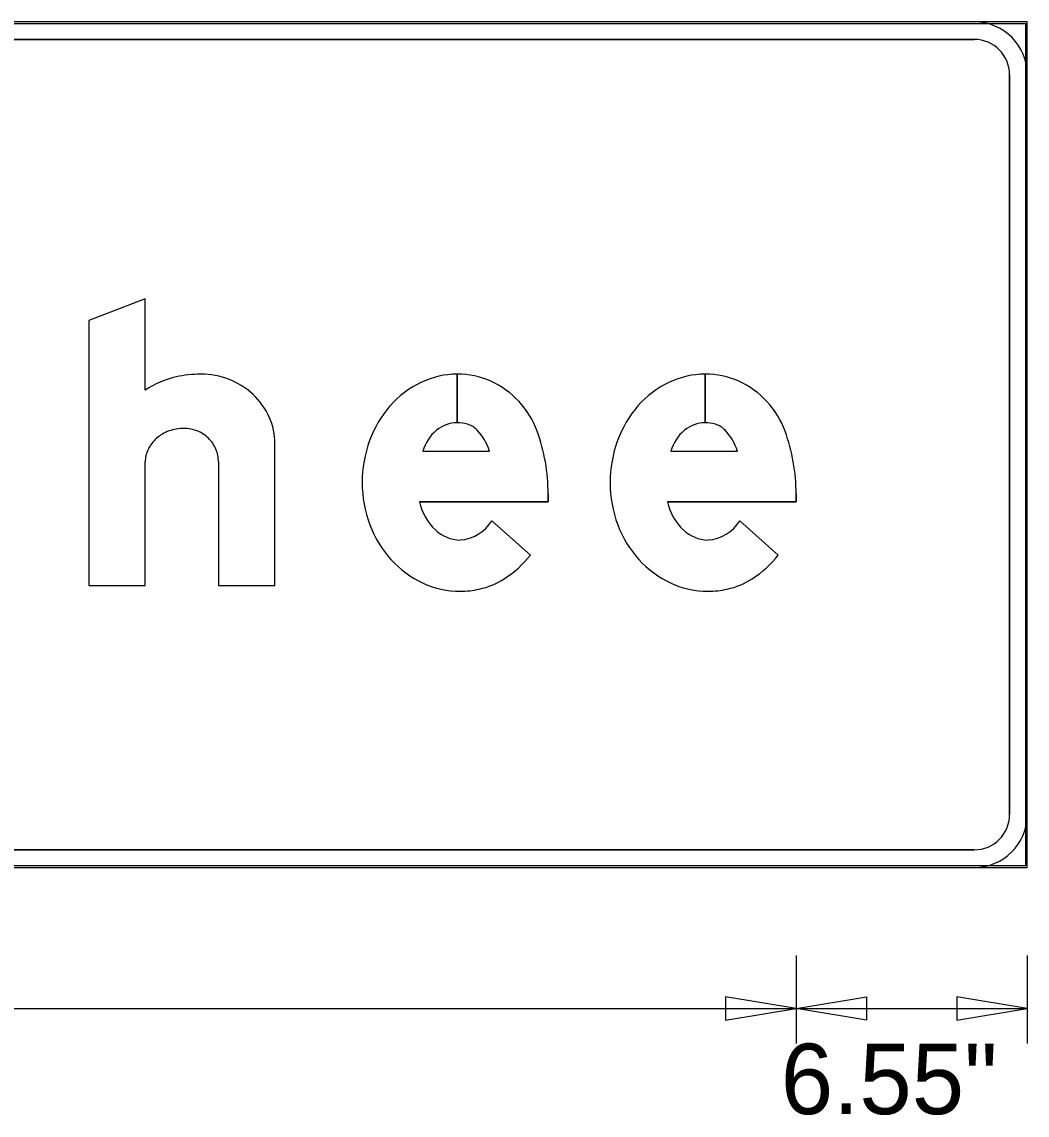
# Model space of a CAD drawing. Extents: x 1374 to 1480, y 568 to 638.
# Drawn here: x 1420.479 to 1422.858, y 581.697 to 584.283 of the extents above; entities that cross this region are included whole.
import ezdxf

# ---------------------------------------------------------------- set-up
doc = ezdxf.new("R2010")
doc.units = 0
for name, color, linetype in [('GSBWFill', 7, 'Continuous'), ('GSColorFill', 7, 'Continuous'), ('GSDims', 7, 'Continuous'), ('GSOutline', 7, 'Continuous')]:
    doc.layers.add(name, color=color, linetype=linetype)

msp = doc.modelspace()

# ---------------------------------------------------------------- linework, layer by layer
at = {"layer": 'GSBWFill'}
for p, q in [((1422.8581, 584.2826), (1415.8581, 584.2826)), ((1422.7331, 584.2826), (1415.9831, 584.2826)), ((1422.8581, 582.2826), (1422.8581, 584.2826)), ((1415.9831, 584.2409), (1422.7331, 584.2409)), ((1422.8164, 584.1576), (1422.8164, 582.4076)), ((1422.8581, 582.4076), (1422.8581, 584.1576)), ((1421.5094, 583.4492), (1421.5094, 583.3342)), ((1421.5094, 583.3342), (1421.5094, 583.4492)), ((1422.0961, 583.4492), (1422.0961, 583.3342)), ((1422.0961, 583.3342), (1422.0961, 583.4492)), ((1421.4281, 583.2674), (1421.586, 583.2674)), ((1422.0147, 583.2674), (1422.1727, 583.2674)), ((1421.5913, 583.1023), (1421.6826, 583.0215)), ((1422.178, 583.1023), (1422.2693, 583.0215)), ((1422.7331, 582.3242), (1415.9835, 582.3242)), ((1415.8581, 582.2826), (1422.8581, 582.2826)), ((1415.9835, 582.2826), (1422.7331, 582.2826))]:
    msp.add_line(p, q, dxfattribs=at)
for points in [[(1420.7714, 583.4118), (1420.7714, 583.6276), (1420.6381, 583.5761), (1420.6381, 582.9492), (1420.7714, 582.9492), (1420.7714, 583.2416)], [(1420.9447, 583.2416), (1420.9447, 582.9492), (1421.0781, 582.9492), (1421.0781, 583.2855)], [(1421.7247, 583.1664), (1421.7247, 583.1474), (1421.4205, 583.1474)], [(1422.3114, 583.1664), (1422.3114, 583.1474), (1422.0071, 583.1474)]]:
    msp.add_lwpolyline(points, dxfattribs=at)
for centre, radius, start, end in [((1422.7331, 584.1576), 0.125, 0, 90), ((1422.7331, 584.1576), 0.0833, 0, 90), ((1422.7331, 582.4076), 0.125, 270, 0), ((1422.7331, 582.4076), 0.0833, 270, 0)]:
    msp.add_arc(centre, radius, start, end, dxfattribs=at)
for centre, major_axis, start_param, end_param in [((1420.9004, 583.2093), (0, 0.2401), 0.235088, 0.567132), ((1420.9026, 583.1825), (0, 0.2667), 0, 0.219986), ((1420.9026, 583.2615), (0, 0.1877), 5.914285, 6.283185), ((1421.5094, 583.2518), (0, 0.1975), 0, 0.44196), ((1421.5094, 583.2518), (0, 0.1975), 5.868518, 6.283016), ((1422.0961, 583.2518), (0, 0.1975), 0, 0.44196), ((1422.0961, 583.2518), (0, 0.1975), 5.868518, 6.283016), ((1420.9072, 583.2732), (0, 0.1752), 5.532258, 5.914285), ((1421.523, 583.2231), (0, 0.2292), 0.44196, 0.851746), ((1421.5044, 583.2439), (0, 0.2067), 5.061282, 5.861635), ((1422.1096, 583.2231), (0, 0.2292), 0.44196, 0.851746), ((1422.0911, 583.2439), (0, 0.2067), 5.061282, 5.861635), ((1420.9141, 583.2807), (0, 0.1649), 5.130076, 5.532258), ((1421.5441, 583.2046), (0, 0.2573), 0.851746, 1.222943), ((1422.1308, 583.2046), (0, 0.2573), 0.851746, 1.222943), ((1420.925, 583.2855), (0, 0.1531), 4.712389, 5.130076), ((1420.8584, 583.2286), (0, 0.0917), 0.345704, 0.715718), ((1420.8629, 583.2162), (0, 0.105), 0, 0.345704), ((1420.8629, 583.2369), (0, 0.0842), 5.900624, 6.283185), ((1420.8638, 583.2392), (0, 0.0818), 5.51227, 5.900624), ((1421.5283, 583.2369), (0, 0.1047), 0.703138, 1.275447), ((1421.5094, 583.2569), (0, 0.0773), 0, 0.684319), ((1421.5094, 583.2446), (0, 0.0896), 6.008019, 6.282813), ((1421.5202, 583.2827), (0, 0.05), 5.468651, 6.008019), ((1421.4606, 583.2265), (0, 0.132), 5.027692, 5.468651), ((1421.2914, 583.1664), (0, 0.4333), 4.712389, 5.061282), ((1422.115, 583.2369), (0, 0.1047), 0.703138, 1.275447), ((1422.0961, 583.2569), (0, 0.0773), 0, 0.684319), ((1422.0961, 583.2446), (0, 0.0896), 6.008019, 6.282813), ((1422.1068, 583.2827), (0, 0.05), 5.468651, 6.008019), ((1422.0472, 583.2265), (0, 0.132), 5.027692, 5.468651), ((1421.8781, 583.1664), (0, 0.4333), 4.712389, 5.061282), ((1420.8515, 583.2365), (0, 0.0812), 0.715718, 1.126231), ((1420.8652, 583.2407), (0, 0.0797), 5.115435, 5.51227), ((1421.5773, 583.1926), (0, 0.2926), 1.222943, 1.570796), ((1422.164, 583.1926), (0, 0.2926), 1.222943, 1.570796), ((1420.8408, 583.2416), (0, 0.0694), 1.126231, 1.570796), ((1420.8674, 583.2416), (0, 0.0773), 4.712389, 5.115435), ((1421.5685, 583.1926), (0, 0.2838), 1.570796, 1.928626), ((1422.1552, 583.1926), (0, 0.2838), 1.570796, 1.928626), ((1421.5486, 583.1757), (0, 0.1312), 1.788032, 2.378697), ((1422.1352, 583.1757), (0, 0.1312), 1.788032, 2.378697), ((1421.5099, 583.1526), (0, 0.0957), 3.209537, 4.158837), ((1422.0966, 583.1526), (0, 0.0957), 3.209537, 4.158837), ((1421.5431, 583.1831), (0, 0.2567), 1.928626, 2.305123), ((1421.5176, 583.1439), (0, 0.0868), 2.383204, 3.128268), ((1422.1298, 583.1831), (0, 0.2567), 1.928626, 2.305123), ((1422.1043, 583.1439), (0, 0.0868), 2.383204, 3.128268), ((1421.5269, 583.1684), (0, 0.2348), 2.305123, 2.711411), ((1421.4872, 583.1746), (0, 0.2483), 3.710413, 4.047817), ((1422.1135, 583.1684), (0, 0.2348), 2.305123, 2.711411), ((1422.0738, 583.1746), (0, 0.2483), 3.710413, 4.047817), ((1421.5164, 583.1457), (0, 0.2098), 2.711411, 3.141593), ((1421.5221, 583.1199), (0, 0.1833), 3.35931, 3.710413), ((1422.1031, 583.1457), (0, 0.2098), 2.711411, 3.141593), ((1422.1088, 583.1199), (0, 0.1833), 3.35931, 3.710413), ((1421.5164, 583.1457), (0, 0.2098), 3.141593, 3.35931), ((1422.1031, 583.1457), (0, 0.2098), 3.141593, 3.35931)]:
    msp.add_ellipse(centre, major_axis=major_axis, ratio=0.999996, start_param=start_param, end_param=end_param, dxfattribs=at)
at = {"layer": 'GSColorFill'}
for p, q in [((1422.8581, 584.2826), (1415.8581, 584.2826)), ((1422.8581, 584.2826), (1415.8581, 584.2826)), ((1415.8622, 584.2784), (1422.8539, 584.2784)), ((1422.7331, 584.2826), (1415.9831, 584.2826)), ((1422.8539, 584.2784), (1422.8539, 582.2867)), ((1422.8581, 582.2826), (1422.8581, 584.2826)), ((1422.8581, 582.2826), (1422.8581, 584.2826)), ((1415.9831, 584.2409), (1422.7331, 584.2409)), ((1422.8164, 584.1576), (1422.8164, 582.4076)), ((1422.8581, 582.4076), (1422.8581, 584.1576)), ((1421.5094, 583.4492), (1421.5094, 583.3342)), ((1421.5094, 583.3342), (1421.5094, 583.4492)), ((1422.0961, 583.4492), (1422.0961, 583.3342)), ((1422.0961, 583.3342), (1422.0961, 583.4492)), ((1421.4281, 583.2674), (1421.586, 583.2674)), ((1422.0147, 583.2674), (1422.1727, 583.2674)), ((1421.5913, 583.1023), (1421.6826, 583.0215)), ((1422.178, 583.1023), (1422.2693, 583.0215)), ((1422.7331, 582.3242), (1415.9835, 582.3242)), ((1422.8539, 582.2867), (1415.8581, 582.2867)), ((1415.8581, 582.2826), (1422.8581, 582.2826)), ((1415.8581, 582.2826), (1422.8581, 582.2826)), ((1415.9835, 582.2826), (1422.7331, 582.2826))]:
    msp.add_line(p, q, dxfattribs=at)
for points in [[(1420.7714, 583.4118), (1420.7714, 583.6276), (1420.6381, 583.5761), (1420.6381, 582.9492), (1420.7714, 582.9492), (1420.7714, 583.2416)], [(1420.9447, 583.2416), (1420.9447, 582.9492), (1421.0781, 582.9492), (1421.0781, 583.2855)], [(1421.7247, 583.1664), (1421.7247, 583.1474), (1421.4205, 583.1474)], [(1422.3114, 583.1664), (1422.3114, 583.1474), (1422.0071, 583.1474)]]:
    msp.add_lwpolyline(points, dxfattribs=at)
for centre, radius, start, end in [((1422.7331, 584.1576), 0.125, 0, 90), ((1422.7331, 584.1576), 0.0833, 0, 90), ((1422.7331, 582.4076), 0.125, 270, 0), ((1422.7331, 582.4076), 0.0833, 270, 0)]:
    msp.add_arc(centre, radius, start, end, dxfattribs=at)
for centre, major_axis, start_param, end_param in [((1420.9004, 583.2093), (0, 0.2401), 0.235088, 0.567132), ((1420.9026, 583.1825), (0, 0.2667), 0, 0.219986), ((1420.9026, 583.2615), (0, 0.1877), 5.914285, 6.283185), ((1421.5094, 583.2518), (0, 0.1975), 0, 0.44196), ((1421.5094, 583.2518), (0, 0.1975), 5.868518, 6.283016), ((1422.0961, 583.2518), (0, 0.1975), 0, 0.44196), ((1422.0961, 583.2518), (0, 0.1975), 5.868518, 6.283016), ((1420.9072, 583.2732), (0, 0.1752), 5.532258, 5.914285), ((1421.523, 583.2231), (0, 0.2292), 0.44196, 0.851746), ((1421.5044, 583.2439), (0, 0.2067), 5.061282, 5.861635), ((1422.1096, 583.2231), (0, 0.2292), 0.44196, 0.851746), ((1422.0911, 583.2439), (0, 0.2067), 5.061282, 5.861635), ((1420.9141, 583.2807), (0, 0.1649), 5.130076, 5.532258), ((1421.5441, 583.2046), (0, 0.2573), 0.851746, 1.222943), ((1422.1308, 583.2046), (0, 0.2573), 0.851746, 1.222943), ((1420.925, 583.2855), (0, 0.1531), 4.712389, 5.130076), ((1420.8584, 583.2286), (0, 0.0917), 0.345704, 0.715718), ((1420.8629, 583.2162), (0, 0.105), 0, 0.345704), ((1420.8629, 583.2369), (0, 0.0842), 5.900624, 6.283185), ((1420.8638, 583.2392), (0, 0.0818), 5.51227, 5.900624), ((1421.5283, 583.2369), (0, 0.1047), 0.703138, 1.275447), ((1421.5094, 583.2569), (0, 0.0773), 0, 0.684319), ((1421.5094, 583.2446), (0, 0.0896), 6.008019, 6.282813), ((1421.5202, 583.2827), (0, 0.05), 5.468651, 6.008019), ((1421.4606, 583.2265), (0, 0.132), 5.027692, 5.468651), ((1421.2914, 583.1664), (0, 0.4333), 4.712389, 5.061282), ((1422.115, 583.2369), (0, 0.1047), 0.703138, 1.275447), ((1422.0961, 583.2569), (0, 0.0773), 0, 0.684319), ((1422.0961, 583.2446), (0, 0.0896), 6.008019, 6.282813), ((1422.1068, 583.2827), (0, 0.05), 5.468651, 6.008019), ((1422.0472, 583.2265), (0, 0.132), 5.027692, 5.468651), ((1421.8781, 583.1664), (0, 0.4333), 4.712389, 5.061282), ((1420.8515, 583.2365), (0, 0.0812), 0.715718, 1.126231), ((1420.8652, 583.2407), (0, 0.0797), 5.115435, 5.51227), ((1421.5773, 583.1926), (0, 0.2926), 1.222943, 1.570796), ((1422.164, 583.1926), (0, 0.2926), 1.222943, 1.570796), ((1420.8408, 583.2416), (0, 0.0694), 1.126231, 1.570796), ((1420.8674, 583.2416), (0, 0.0773), 4.712389, 5.115435), ((1421.5685, 583.1926), (0, 0.2838), 1.570796, 1.928626), ((1422.1552, 583.1926), (0, 0.2838), 1.570796, 1.928626), ((1421.5486, 583.1757), (0, 0.1312), 1.788032, 2.378697), ((1422.1352, 583.1757), (0, 0.1312), 1.788032, 2.378697), ((1421.5099, 583.1526), (0, 0.0957), 3.209537, 4.158837), ((1422.0966, 583.1526), (0, 0.0957), 3.209537, 4.158837), ((1421.5431, 583.1831), (0, 0.2567), 1.928626, 2.305123), ((1421.5176, 583.1439), (0, 0.0868), 2.383204, 3.128268), ((1422.1298, 583.1831), (0, 0.2567), 1.928626, 2.305123), ((1422.1043, 583.1439), (0, 0.0868), 2.383204, 3.128268), ((1421.5269, 583.1684), (0, 0.2348), 2.305123, 2.711411), ((1421.4872, 583.1746), (0, 0.2483), 3.710413, 4.047817), ((1422.1135, 583.1684), (0, 0.2348), 2.305123, 2.711411), ((1422.0738, 583.1746), (0, 0.2483), 3.710413, 4.047817), ((1421.5164, 583.1457), (0, 0.2098), 2.711411, 3.141593), ((1421.5221, 583.1199), (0, 0.1833), 3.35931, 3.710413), ((1422.1031, 583.1457), (0, 0.2098), 2.711411, 3.141593), ((1422.1088, 583.1199), (0, 0.1833), 3.35931, 3.710413), ((1421.5164, 583.1457), (0, 0.2098), 3.141593, 3.35931), ((1422.1031, 583.1457), (0, 0.2098), 3.141593, 3.35931)]:
    msp.add_ellipse(centre, major_axis=major_axis, ratio=0.999996, start_param=start_param, end_param=end_param, dxfattribs=at)
at = {"layer": 'GSDims'}
for p, q in [((1422.3114, 582.0742), (1422.3114, 581.8659)), ((1422.3114, 582.0742), (1422.3114, 581.8659)), ((1422.8581, 582.0742), (1422.8581, 581.8659)), ((1422.8581, 582.0742), (1422.8581, 581.8659)), ((1416.4047, 581.9492), (1422.3114, 581.9492)), ((1422.3114, 581.9492), (1422.8581, 581.9492))]:
    msp.add_line(p, q, dxfattribs=at)
for points in [[(1422.3114, 581.9492), (1422.1447, 581.977), (1422.1447, 581.9215)], [(1422.3114, 581.9492), (1422.4781, 581.977), (1422.4781, 581.9215)], [(1422.8581, 581.9492), (1422.6914, 581.977), (1422.6914, 581.9215)]]:
    msp.add_lwpolyline(points, close=True, dxfattribs=at)
at = {"layer": 'GSOutline'}
for p, q in [((1422.8581, 584.2826), (1415.8581, 584.2826)), ((1422.7331, 584.2826), (1415.9831, 584.2826)), ((1422.8581, 582.2826), (1422.8581, 584.2826)), ((1422.7331, 584.2409), (1415.9831, 584.2409)), ((1422.8164, 582.4076), (1422.8164, 584.1576)), ((1422.8581, 582.4076), (1422.8581, 584.1576)), ((1421.4281, 583.2674), (1421.586, 583.2674)), ((1422.0147, 583.2674), (1422.1727, 583.2674)), ((1421.6826, 583.0215), (1421.5913, 583.1023)), ((1422.2693, 583.0215), (1422.178, 583.1023)), ((1415.9831, 582.3242), (1422.7331, 582.3242)), ((1415.8581, 582.2826), (1422.8581, 582.2826)), ((1415.9831, 582.2826), (1422.7331, 582.2826))]:
    msp.add_line(p, q, dxfattribs=at)
for points in [[(1420.7714, 583.4118), (1420.7714, 583.6276), (1420.6381, 583.5761), (1420.6381, 582.9492), (1420.7714, 582.9492), (1420.7714, 583.2416)], [(1420.9447, 583.2416), (1420.9447, 582.9492), (1421.0781, 582.9492), (1421.0781, 583.2855)], [(1421.4205, 583.1474), (1421.7247, 583.1474), (1421.7247, 583.1664)], [(1422.0071, 583.1474), (1422.3114, 583.1474), (1422.3114, 583.1664)]]:
    msp.add_lwpolyline(points, dxfattribs=at)
for centre, radius, start, end in [((1422.7331, 584.1576), 0.125, 0, 90), ((1422.7331, 584.1576), 0.0833, 0, 90), ((1422.7331, 582.4076), 0.125, 270, 0), ((1422.7331, 582.4076), 0.0833, 270, 0)]:
    msp.add_arc(centre, radius, start, end, dxfattribs=at)
for centre, major_axis, start_param, end_param in [((1420.9004, 583.2093), (0, 0.2401), 0.235088, 0.567132), ((1420.9026, 583.1825), (0, 0.2667), 0, 0.219986), ((1420.9026, 583.2615), (0, 0.1877), 5.914285, 6.283185), ((1421.5094, 583.2518), (0, 0.1975), 0, 0.44196), ((1421.5094, 583.2518), (0, 0.1975), 5.868518, 6.283185), ((1422.0961, 583.2518), (0, 0.1975), 0, 0.44196), ((1422.0961, 583.2518), (0, 0.1975), 5.868518, 6.283185), ((1420.9072, 583.2732), (0, 0.1752), 5.532258, 5.914285), ((1421.523, 583.2231), (0, 0.2292), 0.44196, 0.851746), ((1421.5044, 583.2439), (0, 0.2067), 5.061282, 5.861635), ((1422.1096, 583.2231), (0, 0.2292), 0.44196, 0.851746), ((1422.0911, 583.2439), (0, 0.2067), 5.061282, 5.861635), ((1420.9141, 583.2807), (0, 0.1649), 5.130076, 5.532258), ((1421.5441, 583.2046), (0, 0.2573), 0.851746, 1.222943), ((1422.1308, 583.2046), (0, 0.2573), 0.851746, 1.222943), ((1420.925, 583.2855), (0, 0.1531), 4.712389, 5.130076), ((1420.8584, 583.2286), (0, 0.0917), 0.345704, 0.715718), ((1420.8629, 583.2162), (0, 0.105), 0, 0.345704), ((1420.8629, 583.2369), (0, 0.0842), 5.900624, 6.283185), ((1420.8638, 583.2392), (0, 0.0818), 5.51227, 5.900624), ((1421.5283, 583.2369), (0, 0.1047), 0.703138, 1.275447), ((1421.5094, 583.2569), (0, 0.0773), 0, 0.684319), ((1421.5094, 583.2446), (0, 0.0896), 6.008019, 6.283185), ((1421.5202, 583.2827), (0, 0.05), 5.468651, 6.008019), ((1421.4606, 583.2265), (0, 0.132), 5.027692, 5.468651), ((1421.2914, 583.1664), (0, 0.4333), 4.712389, 5.061282), ((1422.115, 583.2369), (0, 0.1047), 0.703138, 1.275447), ((1422.0961, 583.2569), (0, 0.0773), 0, 0.684319), ((1422.0961, 583.2446), (0, 0.0896), 6.008019, 6.283185), ((1422.1068, 583.2827), (0, 0.05), 5.468651, 6.008019), ((1422.0472, 583.2265), (0, 0.132), 5.027692, 5.468651), ((1421.8781, 583.1664), (0, 0.4333), 4.712389, 5.061282), ((1420.8515, 583.2365), (0, 0.0812), 0.715718, 1.126231), ((1420.8652, 583.2407), (0, 0.0797), 5.115435, 5.51227), ((1421.5773, 583.1926), (0, 0.2926), 1.222943, 1.570796), ((1422.164, 583.1926), (0, 0.2926), 1.222943, 1.570796), ((1420.8408, 583.2416), (0, 0.0694), 1.126231, 1.570796), ((1420.8674, 583.2416), (0, 0.0773), 4.712389, 5.115435), ((1421.5685, 583.1926), (0, 0.2838), 1.570796, 1.928626), ((1422.1552, 583.1926), (0, 0.2838), 1.570796, 1.928626), ((1421.5486, 583.1757), (0, 0.1312), 1.788032, 2.378697), ((1422.1352, 583.1757), (0, 0.1312), 1.788032, 2.378697), ((1421.5099, 583.1526), (0, 0.0957), 3.209537, 4.158837), ((1422.0966, 583.1526), (0, 0.0957), 3.209537, 4.158837), ((1421.5431, 583.1831), (0, 0.2567), 1.928626, 2.305123), ((1421.5176, 583.1439), (0, 0.0868), 2.383204, 3.128268), ((1422.1298, 583.1831), (0, 0.2567), 1.928626, 2.305123), ((1422.1043, 583.1439), (0, 0.0868), 2.383204, 3.128268), ((1421.5269, 583.1684), (0, 0.2348), 2.305123, 2.711411), ((1421.4872, 583.1746), (0, 0.2483), 3.710413, 4.047817), ((1422.1135, 583.1684), (0, 0.2348), 2.305123, 2.711411), ((1422.0738, 583.1746), (0, 0.2483), 3.710413, 4.047817), ((1421.5164, 583.1457), (0, 0.2098), 2.711411, 3.141593), ((1421.5221, 583.1199), (0, 0.1833), 3.35931, 3.710413), ((1422.1031, 583.1457), (0, 0.2098), 2.711411, 3.141593), ((1422.1088, 583.1199), (0, 0.1833), 3.35931, 3.710413), ((1421.5164, 583.1457), (0, 0.2098), 3.141593, 3.35931), ((1422.1031, 583.1457), (0, 0.2098), 3.141593, 3.35931)]:
    msp.add_ellipse(centre, major_axis=major_axis, ratio=0.999996, start_param=start_param, end_param=end_param, dxfattribs=at)

# ---------------------------------------------------------------- texts
at = {"layer": 'GSDims'}
msp.add_text('6.55"', height=0.16667, dxfattribs=at).set_placement((1422.2752, 581.6992))

doc.saveas('drawing.dxf')
